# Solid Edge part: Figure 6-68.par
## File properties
Author: TIET
Template: Iso Metric Part.par
Last saved by: CADCIM
Revision: 4
Application: Solid Edge
Accuracy: 0.990
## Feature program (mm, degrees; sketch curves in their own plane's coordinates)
pattern "unnamed Pattern 1"
Other named dimensions: "Pattern_3": XOffset = 60 deg
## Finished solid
Body 1: solid body, 12 faces, 23 edges, 8 vertices.
  Faces by surface: cylinder 7, plane 5
  Edges by curve: circle 15, line 8
Bounding box of the edges (mm): 106.295 x 6.758 x 106.295, from (-53.1477, -3.3791, -53.1477) to (53.1477, 3.3791, 53.1477).
Cylindrical faces by radius (mm): R3.7218 x4, R16.5187 x1, R34.3496 x1, R53.1477 x1
Planar faces by outward normal: +y 1, -x 1, -y 2, oblique 1
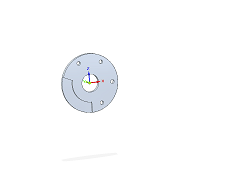
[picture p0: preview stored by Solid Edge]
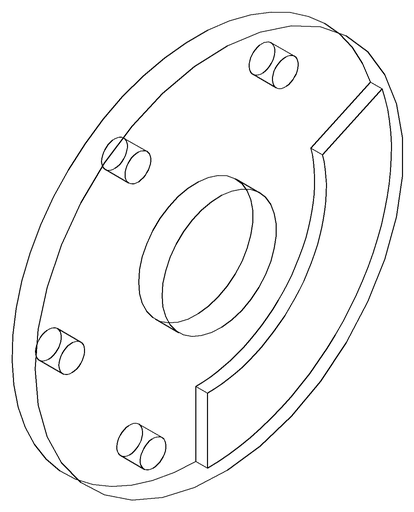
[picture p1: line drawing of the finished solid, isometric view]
